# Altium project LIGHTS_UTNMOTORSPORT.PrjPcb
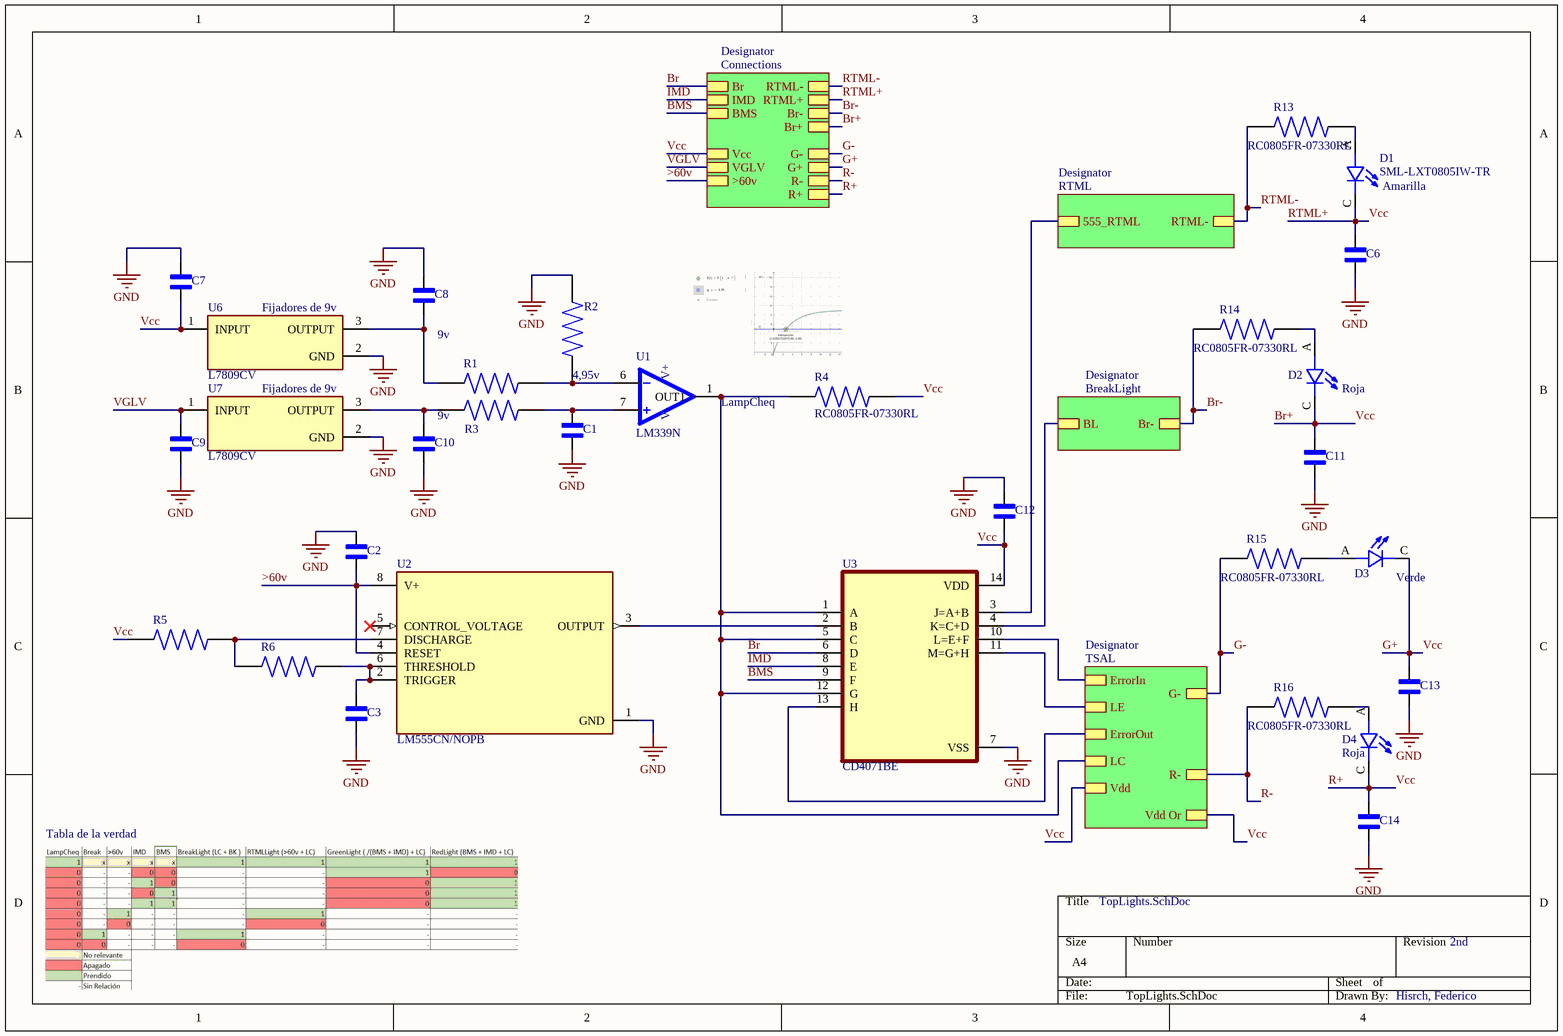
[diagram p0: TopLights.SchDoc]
5 sheets, 55 parts. Net scope: hierarchical (ports join the sheet entries above them; power ports are global).
Sheets:
  TopLights.SchDoc
    Designator = BreakLight.SchDoc
    Designator = RTML.SchDoc
    Designator = TSAL.SchDoc
    Designator = Connections.SchDoc

## Sheet TopLights.SchDoc
size A4; SheetNumber: 1; SheetTotal: 5

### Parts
C1  08055C104M4T2A  [CAPC2012X140N]  (value not drawn)
C2  08055C104M4T2A  [CAPC2012X140N]  (value not drawn)
C3  08055C104M4T2A  [CAPC2012X140N]  (value not drawn)
C6  08055C104M4T2A  [CAPC2012X140N]  (value not drawn)
C7  08055C104M4T2A  [CAPC2012X140N]  (value not drawn)
C8  08055C104M4T2A  [CAPC2012X140N]  (value not drawn)
C9  08055C104M4T2A  [CAPC2012X140N]  (value not drawn)
C10  08055C104M4T2A  [CAPC2012X140N]  (value not drawn)
C11  08055C104M4T2A  [CAPC2012X140N]  (value not drawn)
C12  08055C104M4T2A  [CAPC2012X140N]  (value not drawn)
C13  08055C104M4T2A  [CAPC2012X140N]  (value not drawn)
C14  08055C104M4T2A  [CAPC2012X140N]  (value not drawn)
D1  SML-LXT0805IW-TR  [LEDC2012X120N]
D2  SML-LXT0805IW-TR  [LEDC2012X120N]  (value not drawn)
D3  SML-LXT0805IW-TR  [LEDC2012X120N]  (value not drawn)
D4  SML-LXT0805IW-TR  [LEDC2012X120N]  (value not drawn)
R1  RC0805FR-07330RL  [RESC2012X60N]  (value not drawn)
R2  RC0805FR-07330RL  [RESC2012X60N]  (value not drawn)
R3  RC0805FR-07330RL  [RESC2012X60N]  (value not drawn)
R4  RC0805FR-07330RL  [RESC2012X60N]
R5  RC0805FR-07330RL  [RESC2012X60N]  (value not drawn)
R6  RC0805FR-07330RL  [RESC2012X60N]  (value not drawn)
R13  RC0805FR-07330RL  [RESC2012X60N]
R14  RC0805FR-07330RL  [RESC2012X60N]
R15  RC0805FR-07330RL  [RESC2012X60N]
R16  RC0805FR-07330RL  [RESC2012X60N]
U1  LM339N  [DIP764W47P254L1920H431Q14]
U2  LM555CN/NOPB  [DIP794W45P254L959H508Q8]
U3  CD4071BE  [DIP794W45P254L1969H508Q14]
U6  L7809CV  [TO255P1020X450X1968-3B]
U7  L7809CV  [TO255P1020X450X1968-3B]

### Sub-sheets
Designator = BreakLight: BL, Br-
Designator = RTML: 555_RTML, RTML-
Designator = TSAL: ErrorIn, ErrorOut, G-, R-, LE, Vdd, LC, Vdd Or
Designator = Connections: Br, IMD, BMS, VGLV, RTML-, RTML+, Br-, >60v, R+, R-, G+, G-, Br+, Vcc

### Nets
GND: C1.2 C2.1 C3.2 C6.2 C7.1 C8.1 C9.2 C10.2 C11.2 C12.1 C13.2 C14.2 R2.2 U2.1(GND) U3.7(VSS) U6.2(GND) U7.2(GND)
>60v: C2.2 U2.4(RESET) U2.8(V+) ; sheet Designator/>60v
BMS: U3.9(F) ; sheet Designator/BMS
Br: U3.6(D) ; sheet Designator/Br
Br+: C6.1 C7.2 C11.1 C12.2 C13.1 C14.1 D1.C D2.C D3.C D4.C R4.2 R5.1 U3.14(VDD) U6.1(INPUT) ; sheet Designator/Vdd, sheet Designator/Vdd Or, sheet Designator/RTML+, sheet Designator/R+, sheet Designator/G+, sheet Designator/Br+, sheet Designator/Vcc  [also labelled G+, R+, RTML+, Vcc]
Br-: R14.2 ; sheet Designator/Br-, sheet Designator/Br-
G-: R15.2 ; sheet Designator/G-, sheet Designator/G-
IMD: U3.8(E) ; sheet Designator/IMD
R-: R16.2 ; sheet Designator/R-, sheet Designator/R-
RTML-: R13.2 ; sheet Designator/RTML-, sheet Designator/RTML-
VGLV: C9.1 U7.1(INPUT) ; sheet Designator/VGLV
NetC1_1: C1.1 R3.2 U1.7(IN1+)
NetC3_1: C3.1 R6.2 U2.2(TRIGGER) U2.6(THRESHOLD)
NetC4_2: U3.10(L=E+F) ; sheet Designator/ErrorIn
NetC8_2: C8.2 R1.1 U6.3(OUTPUT)
NetC10_1: C10.1 R3.1 U7.3(OUTPUT)
NetD1_A: D1.A R13.1
NetD2_A: D2.A R14.1
NetD3_A: D3.A R15.1
NetD4_A: D4.A R16.1
NetQ1_1: U3.4(K=C+D) ; sheet Designator/BL
NetQ2_1: U3.3(J=A+B) ; sheet Designator/555_RTML
NetQ4_1: U3.11(M=G+H) ; sheet Designator/LE
NetR1_2: R1.2 R2.1 U1.6(IN1-)
NetR4_1: R4.1 U1.1(OUT1) U3.1(A) U3.5(C) U3.12(G) ; sheet Designator/LC
NetR5_2: R5.2 R6.1 U2.7(DISCHARGE)
NetU2_3: U2.3(OUTPUT) U3.2(B)
NetU3_13: U3.13(H) ; sheet Designator/ErrorOut

Not connected (* = marked no-connect by the designer): U2 5(CONTROL_VOLTAGE)*

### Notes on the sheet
- (near D1) Amarilla
- (near U6) Fijadores de 9v
- 9v
- (near R2) 4,95v
- (near U7) Fijadores de 9v
- (near U1) LampCheq
- (near D2) Roja
- (near D3) Verde
- (near D4) Roja
- Tabla de la verdad
- TopLights.SchDoc
- 2nd
- Hisrch, Federico

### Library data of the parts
C1 = 08055C104M4T2A: 220uF 50V Ceramic Capacitor X7R 0805 (2012 Metric); MF: AVX
C2 C6 C11-C14 = 08055C104M4T2A: 0.1 ÂµF Â±20% 50V Ceramic Capacitor X7R 0805 (2012 Metric); MF: AVX
C3 = 08055C104M4T2A: 0.11 ÂµF Â±20% 50V Ceramic Capacitor X7R 0805 (2012 Metric); MF: AVX
C7 C9 = 08055C104M4T2A: 0.33uF 50V Ceramic Capacitor X7R 0805 (2012 Metric); MF: AVX
C8 C10 = 08055C104M4T2A: 0.1uF 50V Ceramic Capacitor X7R 0805 (2012 Metric); MF: AVX
D1-D4 = SML-LXT0805IW-TR: LED;Red;11mcd;0.061In.Dia.;SMD;100mA;2V Vf;635nm;140deg;SMD;White Diffused;5V Vr ¦ Lumex SML-LXT0805IW-TR; MF: Lumex Opto/Components
R1 = RC0805FR-07330RL: 8,2kohms, 1/8W Chip Resistor 0805 (2012 Metric) Moisture Resistant Thick Film; MF: Yageo
R2 = RC0805FR-07330RL: 10kohms Chip Resistor 0805 (2012 Metric) Moisture Resistant Thick Film; MF: Yageo
R3 = RC0805FR-07330RL: 15kohm Chip Resistor 0805 (2012 Metric) Moisture Resistant Thick Film; MF: Yageo
R4 = RC0805FR-07330RL: 10kohm, 1/8W Chip Resistor 0805 (2012 Metric) Moisture Resistant Thick Film; MF: Yageo
R5 = RC0805FR-07330RL: 1kohms, 1/8W Chip Resistor 0805 (2012 Metric) Moisture Resistant Thick Film; MF: Yageo
R6 = RC0805FR-07330RL: 6.2M ohms, 1/8W Chip Resistor 0805 (2012 Metric) Moisture Resistant Thick Film; MF: Yageo
R13-R16 = RC0805FR-07330RL: 1kohm, 1/8W Chip Resistor 0805 (2012 Metric) Moisture Resistant Thick Film; MF: Yageo
U1 = LM339N: Quad Voltage Comparators; MF: TAEJIN
U2 = LM555CN/NOPB: Highly Stable 555 Timer; MF: Texas Instruments
U3 = CD4071BE: 4-ch 2-input 3-V to 18-V OR gate; MF: Texas Instruments
U6 U7 = L7809CV: Linear Voltage Regulator IC Positive Fixed 1 Output 1.5A TO-220; MF: STMicroelectronics

## Sheet BreakLight.SchDoc
size A4; SheetNumber: 2; SheetTotal: 5
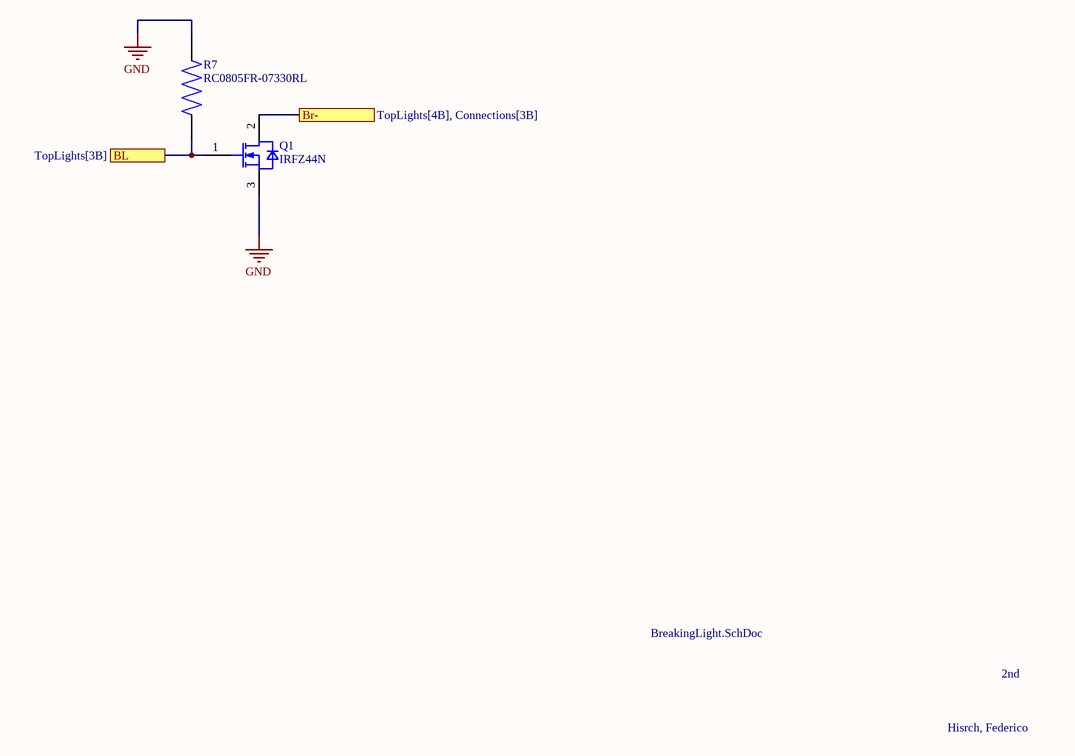
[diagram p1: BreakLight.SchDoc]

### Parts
Q1  IRFZ44N  [IFX-PG-TO220-3-904-1]
R7  RC0805FR-07330RL  [RESC2012X60N]

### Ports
BL (see TopLights[3B]), Br- (see TopLights[4B], Connections[3B])

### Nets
GND: Q1.3(SOURCE) R7.2
Br-: Q1.2(DRAIN) ; port Br-
NetQ1_1: Q1.1(GATE) R7.1 ; port BL

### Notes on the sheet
- BreakingLight.SchDoc
- 2nd
- Hisrch, Federico

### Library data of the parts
Q1 = IRFZ44N: OptiMOS 3 Power-Transistor, VDS 100V; Manufacturer: Infineon Technologies
R7 = RC0805FR-07330RL: 10kohms, 1/8W Chip Resistor 0805 (2012 Metric) Moisture Resistant Thick Film; MF: Yageo

## Sheet RTML.SchDoc
size A4; SheetNumber: 3; SheetTotal: 5
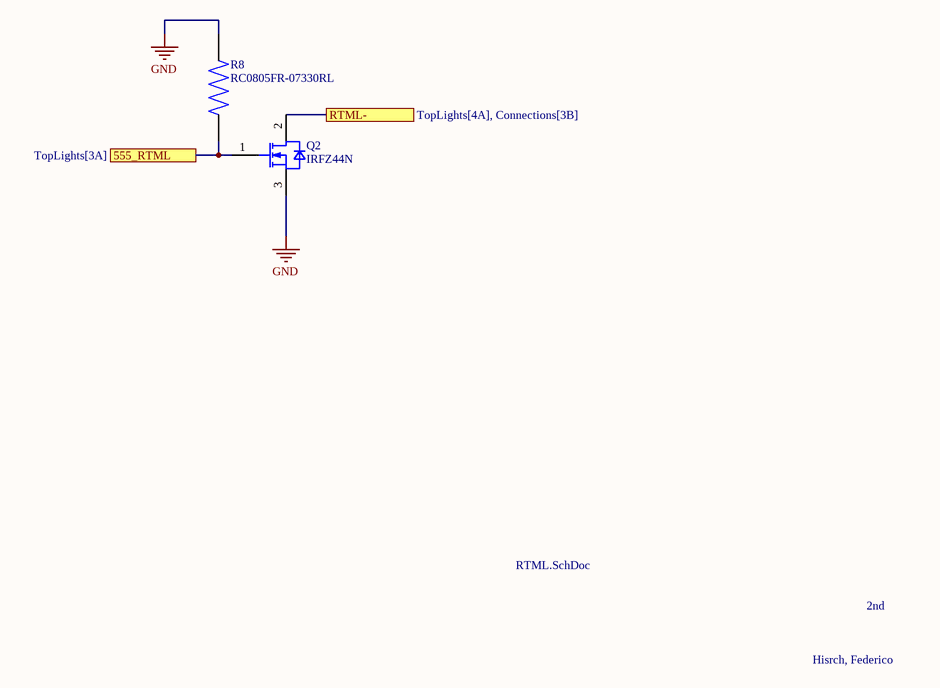
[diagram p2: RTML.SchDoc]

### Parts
Q2  IRFZ44N  [IFX-PG-TO220-3-904-1]
R8  RC0805FR-07330RL  [RESC2012X60N]

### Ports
555_RTML (see TopLights[3A]), RTML- (see TopLights[4A], Connections[3B])

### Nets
GND: Q2.3(SOURCE) R8.2
RTML-: Q2.2(DRAIN) ; port RTML-
NetQ2_1: Q2.1(GATE) R8.1 ; port 555_RTML

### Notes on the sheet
- RTML.SchDoc
- 2nd
- Hisrch, Federico

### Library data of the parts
Q2 = IRFZ44N: as Q1 on sheet BreakLight
R8 = RC0805FR-07330RL: as R7 on sheet BreakLight

## Sheet TSAL.SchDoc
size A4; SheetNumber: 4; SheetTotal: 5
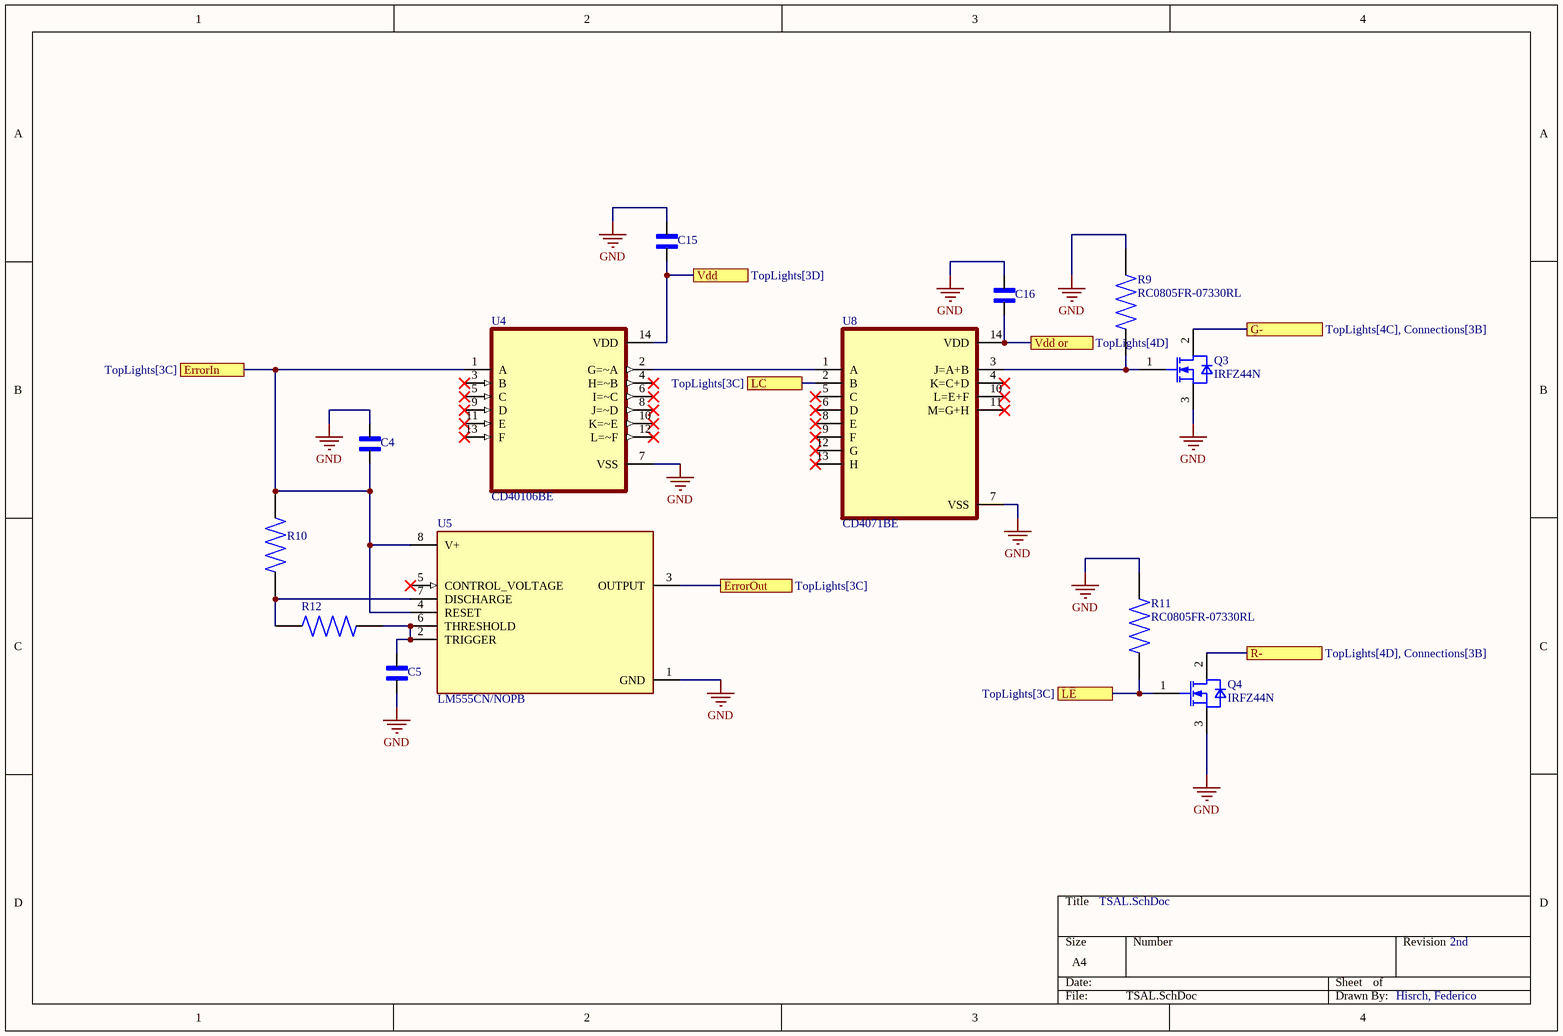
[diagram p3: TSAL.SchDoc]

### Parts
C4  08055C104M4T2A  [CAPC2012X140N]  (value not drawn)
C5  08055C104M4T2A  [CAPC2012X140N]  (value not drawn)
C15  08055C104M4T2A  [CAPC2012X140N]  (value not drawn)
C16  08055C104M4T2A  [CAPC2012X140N]  (value not drawn)
Q3  IRFZ44N  [IFX-PG-TO220-3-904-1]
Q4  IRFZ44N  [IFX-PG-TO220-3-904-1]
R9  RC0805FR-07330RL  [RESC2012X60N]
R10  RC0805FR-07330RL  [RESC2012X60N]  (value not drawn)
R11  RC0805FR-07330RL  [RESC2012X60N]
R12  RC0805FR-07330RL  [RESC2012X60N]  (value not drawn)
U4  CD40106BE  [DIP794W45P254L1969H508Q14]
U5  LM555CN/NOPB  [DIP794W45P254L959H508Q8]
U8  CD4071BE  [DIP794W45P254L1969H508Q14]

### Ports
ErrorIn (see TopLights[3C]), ErrorOut (see TopLights[3C]), G- (see TopLights[4C], Connections[3B]), LC (see TopLights[3C]), LE (see TopLights[3C]), R- (see TopLights[4D], Connections[3B]), Vdd (see TopLights[3D]), Vdd or (see TopLights[4D])

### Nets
GND: C4.1 C5.2 C15.1 C16.1 Q3.3(SOURCE) Q4.3(SOURCE) R9.2 R11.2 U4.7(VSS) U5.1(GND) U8.7(VSS)
Br+: C15.2 C16.2 U4.14(VDD) U8.14(VDD) ; port Vdd, port Vdd or
G-: Q3.2(DRAIN) ; port G-
R-: Q4.2(DRAIN) ; port R-
NetC4_2: C4.2 R10.1 U4.1(A) U5.4(RESET) U5.8(V+) ; port ErrorIn
NetC5_1: C5.1 R12.2 U5.2(TRIGGER) U5.6(THRESHOLD)
NetQ3_1: Q3.1(GATE) R9.1 U8.3(J=A+B)
NetQ4_1: Q4.1(GATE) R11.1 ; port LE
NetR4_1: U8.2(B) ; port LC
NetR10_2: R10.2 R12.1 U5.7(DISCHARGE)
NetU3_13: U5.3(OUTPUT) ; port ErrorOut
NetU4_2: U4.2(G=~A) U8.1(A)

Not connected (* = marked no-connect by the designer): U4 3(B)* 4(H=~B)* 5(C)* 6(I=~C)* 8(J=~D)* 9(D)* 10(K=~E)* 11(E)* 12(L=~F)* 13(F)*; U5 5(CONTROL_VOLTAGE)*; U8 4(K=C+D)* 5(C)* 6(D)* 8(E)* 9(F)* 10(L=E+F)* 11(M=G+H)* 12(G)* 13(H)*

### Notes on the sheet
- TSAL.SchDoc
- 2nd
- Hisrch, Federico

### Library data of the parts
C4 C5 C15 C16 = 08055C104M4T2A: as C2 on sheet TopLights
Q3 Q4 = IRFZ44N: as Q1 on sheet BreakLight
R9 R11 = RC0805FR-07330RL: as R7 on sheet BreakLight
R10 = RC0805FR-07330RL: 1Kohms, 1/8W Chip Resistor 0805 (2012 Metric) Moisture Resistant Thick Film; MF: Yageo
R12 = RC0805FR-07330RL: 1.8Mohms, 1/8W Chip Resistor 0805 (2012 Metric) Moisture Resistant Thick Film; MF: Yageo
U4 = CD40106BE: 6-ch, 3-V to 18-V inverters with Schmitt-Trigger inputs; MF: Texas Instruments
U5 = LM555CN/NOPB: as U2 on sheet TopLights
U8 = CD4071BE: as U3 on sheet TopLights

## Sheet Connections.SchDoc
size A4; SheetNumber: 5; SheetTotal: 5
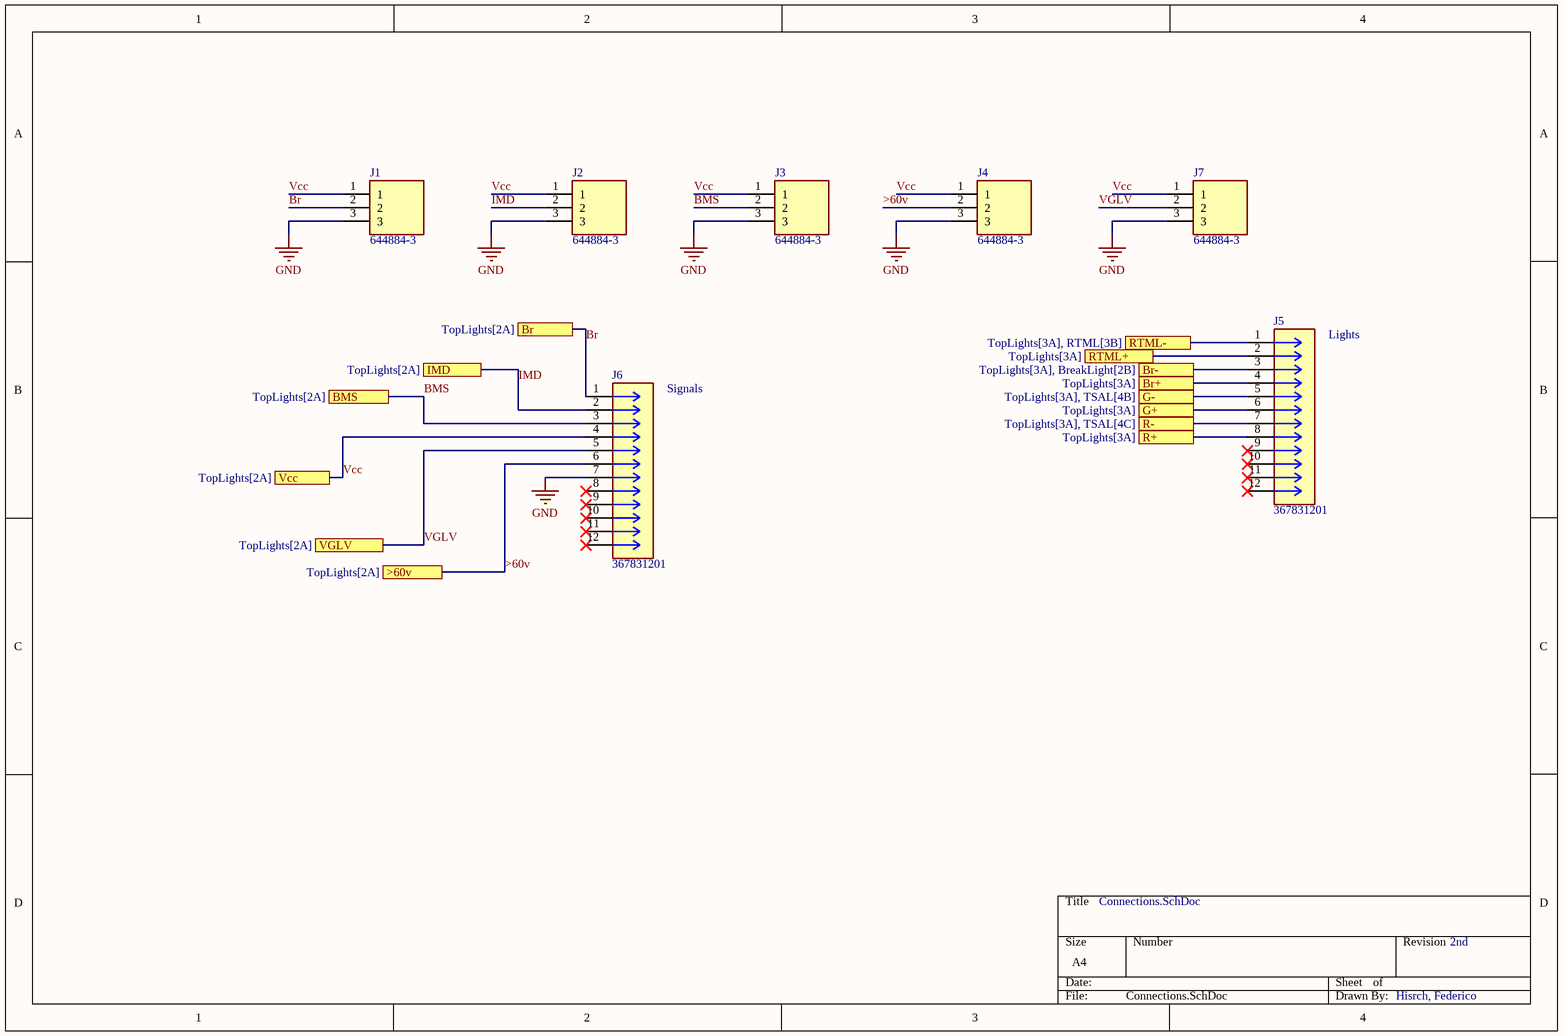
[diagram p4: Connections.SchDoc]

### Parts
J1  644884-3  [TE_644884-3]
J2  644884-3  [TE_644884-3]
J3  644884-3  [TE_644884-3]
J4  644884-3  [TE_644884-3]
J5  367831201  [CONN_3678312XX_MOL]
J6  367831201  [CONN_3678312XX_MOL]
J7  644884-3  [TE_644884-3]

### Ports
>60v (see TopLights[2A]), BMS (see TopLights[2A]), Br (see TopLights[2A]), Br+ (see TopLights[3A]), Br- (see TopLights[3A], BreakLight[2B]), G+ (see TopLights[3A]), G- (see TopLights[3A], TSAL[4B]), IMD (see TopLights[2A]), R+ (see TopLights[3A]), R- (see TopLights[3A], TSAL[4C]), RTML+ (see TopLights[3A]), RTML- (see TopLights[3A], RTML[3B]), Vcc (see TopLights[2A]), VGLV (see TopLights[2A])

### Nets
GND: J1.3 J2.3 J3.3 J4.3 J6.7 J7.3
>60v: J4.2 J6.6 ; port >60v
BMS: J3.2 J6.3 ; port BMS
Br: J1.2 J6.1 ; port Br
Br-: J5.3 ; port Br-
G-: J5.5 ; port G-
IMD: J2.2 J6.2 ; port IMD
R-: J5.7 ; port R-
RTML-: J5.1 ; port RTML-
Vcc: J1.1 J2.1 J3.1 J4.1 J5.2 J5.4 J5.6 J5.8 J6.4 J7.1 ; port RTML+, port Br+, port G+, port R+, port Vcc  [project net Br+]
VGLV: J6.5 J7.2 ; port VGLV

Not connected (* = marked no-connect by the designer): J5 9* 10* 11* 12*; J6 8* 9* 10* 11* 12*

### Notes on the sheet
- Lights
- Signals
- Connections.SchDoc
- 2nd
- Hisrch, Federico

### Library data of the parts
J1-J4 J7 = 644884-3: Conn Unshrouded Header HDR 3 POS 2.54mm Solder ST Thru-Hole Bag/Box; MF: TE Connectivity

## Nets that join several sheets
GND: TopLights (17 pins), BreakLight (Q1.3 R7.2), RTML (Q2.3 R8.2), TSAL (11 pins), Connections (6 pins)
>60v: TopLights (C2.2 U2.4 U2.8), Connections (J4.2 J6.6)
BMS: TopLights (U3.9), Connections (J3.2 J6.3)
Br: TopLights (U3.6), Connections (J1.2 J6.1)
Br+: TopLights (14 pins), TSAL (C15.2 C16.2 U4.14 U8.14), Connections (10 pins)
Br-: TopLights (R14.2), BreakLight (Q1.2), Connections (J5.3)
G-: TopLights (R15.2), TSAL (Q3.2), Connections (J5.5)
IMD: TopLights (U3.8), Connections (J2.2 J6.2)
NetC4_2: TopLights (U3.10), TSAL (5 pins)
NetQ1_1: TopLights (U3.4), BreakLight (Q1.1 R7.1)
NetQ2_1: TopLights (U3.3), RTML (Q2.1 R8.1)
NetQ4_1: TopLights (U3.11), TSAL (Q4.1 R11.1)
NetR4_1: TopLights (5 pins), TSAL (U8.2)
NetU3_13: TopLights (U3.13), TSAL (U5.3)
R-: TopLights (R16.2), TSAL (Q4.2), Connections (J5.7)
RTML-: TopLights (R13.2), RTML (Q2.2), Connections (J5.1)
VGLV: TopLights (C9.1 U7.1), Connections (J6.5 J7.2)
